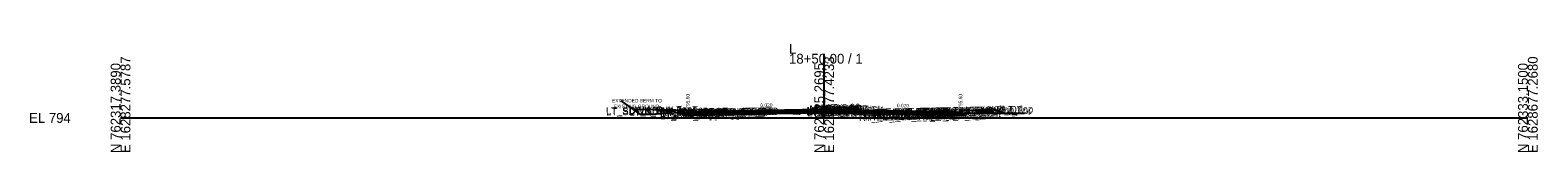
# Model space of a CAD drawing. Extents: x -26 to 4403, y -510 to 9556.
# Drawn here: x -25.7 to 402.8, y 8490.3 to 8521 of the extents above; entities that cross this region are included whole.
import ezdxf

# ---------------------------------------------------------------- set-up
doc = ezdxf.new("R2010")
doc.units = 0
for name, color, linetype in [('Default', 7, 'Continuous'), ('Exist Cross Section Cell', 7, 'Continuous'), ('Exist XS Ground Line', 7, 'Continuous'), ('Exist XS Void Line', 7, 'Continuous'), ('Prop CMT Conc Surface', 7, 'Continuous'), ('Prop CMT Concrete Structures', 7, 'Continuous'), ('Prop CMT Pvmt Course 1', 7, 'Continuous'), ('Prop CMT Pvmt Course 1 CG', 7, 'Continuous'), ('Prop CMT Pvmt Course 2', 7, 'Continuous'), ('Prop CMT Pvmt Course 3', 7, 'Continuous'), ('Prop CMT Pvmt Surface', 7, 'Continuous'), ('Prop CMT Pvmt Wedge Surface 1', 7, 'Continuous'), ('Prop CMT Pvmt Wedge Surface 2', 7, 'Continuous'), ('Prop CMT Pvmt Wedge Surface 3', 7, 'Continuous'), ('Prop CMT Slope Grass', 7, 'Continuous'), ('Prop CMT Subgrade Earthwork', 7, 'Continuous'), ('Prop XS Hydro Elevations', 7, 'Continuous'), ('Prop XS SE Text', 7, 'Continuous'), ('Prop XS Side Slope Text', 7, 'Continuous'), ('Scratch_Level_0', 7, 'Continuous')]:
    doc.layers.add(name, color=color, linetype=linetype)

msp = doc.modelspace()

# ---------------------------------------------------------------- linework, layer by layer
at = {"layer": 'Exist Cross Section Cell'}
for p, q in [((200, 8500), (200, 8518.22)), ((0, 8500), (200, 8500)), ((200, 8500), (400, 8500))]:
    msp.add_line(p, q, dxfattribs=at)
at = {"layer": 'Exist XS Ground Line'}
for p, q in [((142.23, 8504.87), (147.61, 8501.07)), ((147.61, 8501.07), (149.75, 8501.07))]:
    msp.add_line(p, q, dxfattribs=at)
msp.add_lwpolyline([(149.75, 8501.07), (150.28, 8501.1), (160.77, 8501.68), (170.58, 8501.81), (171.07, 8501.81), (172.04, 8501.77), (181.05, 8501.45), (184.18, 8501.38), (191.13, 8501.28), (192.9, 8501.15), (193.71, 8501.58), (195.23, 8501.44), (195.92, 8501.39)], dxfattribs=at)
at = {"layer": 'Exist XS Void Line'}
msp.add_line((195.92, 8501.39), (256.96, 8501.39), dxfattribs=at)
at = {"layer": 'Prop CMT Conc Surface'}
for points in [[(157.75, 8502.21), (152.75, 8502.31)], [(161.25, 8501.6), (161.25, 8502.1), (160.75, 8502.1)], [(238.75, 8501.6), (238.75, 8502.1), (239.25, 8502.1)], [(243.25, 8502.18), (248.25, 8502.28)], [(163.25, 8501.71), (161.25, 8501.6)], [(236.75, 8501.71), (238.75, 8501.6)]]:
    msp.add_lwpolyline(points, dxfattribs=at)
at = {"layer": 'Prop CMT Concrete Structures'}
for points in [[(152.75, 8501.97), (152.75, 8502.31)], [(152.75, 8502.31), (157.75, 8502.21)], [(157.75, 8502.21), (157.75, 8501.87)], [(163.25, 8501.71), (161.25, 8501.6), (161.25, 8502.1), (160.75, 8502.1)], [(160.75, 8502.1), (160.75, 8501.08), (163.25, 8501.13)], [(208, 8502.29), (207.99, 8502.46), (207.24, 8502.71), (206, 8502.97), (204.76, 8502.95), (204.01, 8502.7), (204, 8502.53)], [(204, 8502.53), (208, 8502.29)], [(236.75, 8501.71), (238.75, 8501.6), (238.75, 8502.1), (239.25, 8502.1)], [(239.25, 8502.1), (239.25, 8501.08), (236.75, 8501.13)], [(248.25, 8502.28), (243.25, 8502.18)], [(243.25, 8502.18), (243.25, 8501.85)], [(248.25, 8501.95), (248.25, 8502.28)], [(157.75, 8501.87), (152.75, 8501.97)], [(163.25, 8501.13), (163.25, 8501.71)], [(236.75, 8501.13), (236.75, 8501.71)], [(243.25, 8501.85), (248.25, 8501.95)]]:
    msp.add_lwpolyline(points, dxfattribs=at)
at = {"layer": 'Prop CMT Pvmt Course 1'}
for points in [[(204, 8502.53), (163.25, 8501.71)], [(163.25, 8501.46), (204, 8502.28)], [(175, 8501.7), (204, 8502.28)], [(204, 8502.53), (208, 8502.29)], [(204, 8502.28), (204, 8502.53)], [(204, 8502.28), (204, 8502.53)], [(208, 8502.04), (204, 8502.28)], [(208, 8502.29), (208, 8502.04)], [(208, 8502.29), (236.75, 8501.71)], [(208, 8502.04), (208, 8502.29)], [(163.25, 8501.71), (163.25, 8501.46)], [(236.75, 8501.46), (208, 8502.04)], [(225, 8501.7), (208, 8502.04)], [(236.75, 8501.71), (236.75, 8501.46)]]:
    msp.add_lwpolyline(points, dxfattribs=at)
at = {"layer": 'Prop CMT Pvmt Course 1 CG'}
for points in [[(163.25, 8501.13), (160.25, 8501.07), (159.91, 8500.73)], [(159.91, 8500.73), (163.25, 8500.8)], [(236.75, 8501.13), (239.75, 8501.07), (240.09, 8500.73)], [(236.75, 8500.8), (236.75, 8501.13)], [(240.09, 8500.73), (236.75, 8500.8)]]:
    msp.add_lwpolyline(points, dxfattribs=at)
at = {"layer": 'Prop CMT Pvmt Course 2'}
for points in [[(204, 8502.28), (163.25, 8501.46)], [(204, 8502.28), (175, 8501.7)], [(204, 8502.28), (208, 8502.04)], [(204, 8501.95), (204, 8502.28)], [(204, 8501.95), (204, 8502.28)], [(163.25, 8501.13), (204, 8501.95)], [(163.25, 8501.46), (163.25, 8501.13)], [(175, 8501.37), (204, 8501.95)], [(208, 8501.71), (204, 8501.95)], [(208, 8502.04), (208, 8501.71)], [(208, 8501.71), (208, 8502.04)], [(208, 8502.04), (225, 8501.7)], [(208, 8502.04), (236.75, 8501.46)], [(225, 8501.37), (208, 8501.71)], [(236.75, 8501.13), (208, 8501.71)], [(236.75, 8501.46), (236.75, 8501.13)]]:
    msp.add_lwpolyline(points, dxfattribs=at)
at = {"layer": 'Prop CMT Pvmt Course 3'}
for points in [[(204, 8501.95), (163.25, 8501.13)], [(163.25, 8500.8), (204, 8501.61)], [(163.25, 8501.13), (163.25, 8500.8)], [(204, 8501.95), (175, 8501.37)], [(175, 8501.03), (204, 8501.61)], [(204, 8501.95), (208, 8501.71)], [(204, 8501.61), (204, 8501.95)], [(204, 8501.61), (204, 8501.95)], [(208, 8501.37), (204, 8501.61)], [(208, 8501.71), (208, 8501.37)], [(208, 8501.71), (225, 8501.37)], [(208, 8501.37), (208, 8501.71)], [(208, 8501.71), (236.75, 8501.13)], [(225, 8501.03), (208, 8501.37)], [(236.75, 8500.8), (208, 8501.37)], [(236.75, 8501.13), (236.75, 8500.8)]]:
    msp.add_lwpolyline(points, dxfattribs=at)
at = {"layer": 'Prop CMT Pvmt Surface'}
for points in [[(204, 8502.53), (163.25, 8501.71)], [(204, 8502.53), (208, 8502.29)], [(208, 8502.29), (236.75, 8501.71)]]:
    msp.add_lwpolyline(points, dxfattribs=at)
at = {"layer": 'Prop CMT Pvmt Wedge Surface 1'}
for points in [[(204, 8502.28), (163.25, 8501.46)], [(204, 8502.28), (175, 8501.7)], [(204, 8502.53), (204, 8502.28)], [(208, 8502.29), (208, 8502.04)], [(163.25, 8501.46), (163.25, 8501.71)], [(208, 8502.04), (225, 8501.7)], [(208, 8502.04), (236.75, 8501.46)], [(236.75, 8501.46), (236.75, 8501.71)]]:
    msp.add_lwpolyline(points, dxfattribs=at)
at = {"layer": 'Prop CMT Pvmt Wedge Surface 2'}
for points in [[(204, 8502.53), (204, 8502.28)], [(208, 8502.29), (208, 8502.04)], [(163.25, 8501.46), (163.25, 8501.71)], [(236.75, 8501.46), (236.75, 8501.71)]]:
    msp.add_lwpolyline(points, dxfattribs=at)
at = {"layer": 'Prop CMT Pvmt Wedge Surface 3'}
for points in [[(204, 8502.53), (204, 8501.95)], [(208, 8502.29), (208, 8501.71)], [(163.25, 8501.13), (163.25, 8501.71)], [(236.75, 8501.13), (236.75, 8501.71)]]:
    msp.add_lwpolyline(points, dxfattribs=at)
at = {"layer": 'Prop CMT Slope Grass'}
for points in [[(151.25, 8502.28), (145.74, 8502.4)], [(160.75, 8502.1), (151.25, 8502.28)], [(239.25, 8502.1), (248.25, 8502.27)], [(248.25, 8502.27), (248.74, 8502.28), (251.41, 8501.39)]]:
    msp.add_lwpolyline(points, dxfattribs=at)
at = {"layer": 'Prop CMT Subgrade Earthwork'}
for points in [[(163.25, 8500.8), (159.91, 8500.73), (158.5, 8502.14)], [(236.75, 8500.8), (240.09, 8500.73), (241.5, 8502.14)], [(204, 8501.61), (163.25, 8500.8)], [(163.25, 8500.8), (163.25, 8500.8)], [(163.25, 8500.8), (163.25, 8500.8)], [(163.25, 8500.8), (163.25, 8500.8)], [(163.25, 8500.8), (163.25, 8500.8)], [(204, 8501.61), (208, 8501.37)], [(208, 8501.37), (236.75, 8500.8)]]:
    msp.add_lwpolyline(points, dxfattribs=at)

# ---------------------------------------------------------------- texts
at = {"layer": 'Default'}
msp.add_text('-', height=0.0001, dxfattribs=at).set_placement((0, 8500))
at = {"layer": 'Exist Cross Section Cell'}
for s, p in [('L', (190, 8518.22)), ('18+50.00 / 1', (190, 8515.42)), ('EL 794', (-26, 8498.6))]:
    msp.add_text(s, height=2.8, dxfattribs=at).set_placement(p)
for s, p in [('N 762317.3890', (0, 8490)), ('E 1628277.5787', (2.8, 8490)), ('N 762325.2695', (200, 8490)), ('E 1628477.4233', (202.8, 8490)), ('N 762333.1500', (400, 8490)), ('E 1628677.2680', (402.8, 8490))]:
    msp.add_text(s, height=2.8, rotation=90, dxfattribs=at).set_placement(p)
at = {"layer": 'Prop XS Hydro Elevations'}
for p in [(161.75, 8502.6), (239.25, 8502.6)]:
    msp.add_text('795.60', height=1, rotation=90, dxfattribs=at).set_placement(p)
at = {"layer": 'Prop XS SE Text'}
for rotation, p in [(1.1458, (181.86, 8503.09)), (358.8542, (220.65, 8503.04))]:
    msp.add_text('0.020', height=1, rotation=rotation, dxfattribs=at).set_placement(p)
at = {"layer": 'Prop XS Side Slope Text'}
for s, p in [('EXTENDED BERM TO', (139.68, 8504.39)), ('EXISTING GROUND', (140.19, 8502.76))]:
    msp.add_text(s, height=1, dxfattribs=at).set_placement(p)
msp.add_text('3:1', height=1, rotation=341.5651, dxfattribs=at).set_placement((249.53, 8502.7))
at = {"layer": 'Scratch_Level_0'}
for s, p in [('LT_SDWK_Out_Top', (138.01, 8501.01)), ('LT_SDWK_Out_Bot', (138.04, 8500.68)), ('LT_SDWK_In_Top', (144.63, 8500.94)), ('LT_SDWK_In_Bot', (144.66, 8500.61)), ('LT_PV2_OEOT', (153.45, 8500.27)), ('LT_PV3_OEOT', (153.45, 8499.94)), ('LT_PV1_OEOT', (154.01, 8500.53)), ('LT_PV_Sub_Tie_Out', (159.98, 8500.37)), ('LT_PV_EG_TestPt', (161.43, 8500.4)), ('LT_PV_Sub_Tie_In', (161.57, 8500.4)), ('LT_PV_OEEOP_EG', (162.57, 8500.42)), ('LT_PV_IEEOP_EG', (163.21, 8500.43)), ('LT_Sub_OEEOP', (164.23, 8499.82)), ('LT_PV2_OEEOP', (164.33, 8500.49)), ('LT_PV3_OEEOP', (164.33, 8500.15)), ('LT_Sub_IEEOP', (164.88, 8499.83)), ('LT_PV1_OEEOP', (164.9, 8500.62)), ('LT_PV2_IEEOP', (164.97, 8500.5)), ('LT_PV3_IEEOP', (164.97, 8500.17)), ('LT_PV1_IEEOP', (165.54, 8500.64)), ('LT_PV2_PGL1', (194.9, 8501.1)), ('LT_PV3_PGL1', (194.9, 8500.76)), ('LT_Sub_PGL', (195.14, 8500.44)), ('LT_PV2_PGL', (195.23, 8501.1)), ('LT_PV3_PGL', (195.23, 8500.77)), ('LT_PV4_PGL', (195.23, 8500.44)), ('LT_PV1_PGL', (195.8, 8501.37)), ('MI_Face In', (195.92, 8501.54)), ('MI_Top In', (197.63, 8501.8)), ('MI_Face Out', (198.28, 8501.26)), ('MI_Top Out', (198.49, 8501.53)), ('RT_PV2_PGL1', (198.86, 8500.86)), ('RT_PV3_PGL1', (198.86, 8500.52)), ('MI_Crown', (199.09, 8501.83)), ('RT_Sub_PGL', (199.09, 8500.19)), ('18+50.00', (199.08, 8501.83)), ('RT_PV2_PGL', (199.19, 8500.86)), ('RT_PV3_PGL', (199.19, 8500.53)), ('RT_PV4_PGL', (199.19, 8500.2)), ('MI_Bot Out', (199.28, 8501.12)), ('RT_PV1_PGL', (199.75, 8501.12)), ('18+50.00', (201.39, 8501.48)), ('18+50.00', (201.83, 8501.25)), ('RT_PV_EG_TestPt', (211.38, 8499.83)), ('RT_PV_OEEOP_EG', (212.52, 8499.77)), ('RT_PV_IEEOP_EG', (213.16, 8499.94)), ('RT_Sub_OEEOP', (214.19, 8499.82)), ('RT_PV2_OEEOP', (214.28, 8500.49)), ('RT_PV3_OEEOP', (214.28, 8500.15)), ('RT_Sub_IEEOP', (214.83, 8499.83)), ('RT_PV1_OEEOP', (214.85, 8500.62)), ('RT_PV2_IEEOP', (214.93, 8500.5)), ('RT_PV3_IEEOP', (214.93, 8500.17)), ('RT_PV1_IEEOP', (215.49, 8500.63)), ('RT_Sub_Trench_Out_DLT', (222.04, 8500.75)), ('RT_CG_Top_Face', (225.99, 8500.84)), ('RT_CG1_Shelf_Out', (226.28, 8499.8)), ('RT_CG_Bot_IE', (226.64, 8499.93)), ('RT_PV2_OEOT', (226.9, 8500.27)), ('RT_PV3_OEOT', (226.9, 8499.93)), ('RT_CG_Top_Gut', (226.96, 8500.36)), ('RT_PV1_OEOT', (227.46, 8500.53)), ('RT_CG_Top_BOC', (227.51, 8500.86)), ('RT_CG_Bot_BOC', (227.54, 8499.85)), ('RT_SDWK_In_Top', (231.08, 8500.94)), ('RT_SDWK_In_Bot', (231.12, 8500.61)), ('18+50.00', (231.75, 8500.52)), ('18+50.00', (233.52, 8500.98)), ('RT_SDWK_Out_Top', (234.46, 8501.01)), ('RT_SDWK_Out_Bot', (234.49, 8500.68)), ('RT_Shld_O', (240.81, 8501.13)), ('LT_Sub_OEOT', (153.35, 8499.6)), ('RT_PV_Sub_Tie_Out', (209.91, 8499.09)), ('RT_PV_Sub_Tie_In', (211.56, 8499.29)), ('RT_Sub_OEOT_CG', (224.1, 8499.54)), ('RT_Sub_OEOT', (226.8, 8499.6)), ('RT_Sub_OEOP', (230.17, 8499.53))]:
    msp.add_text(s, height=2, rotation=1.1458, dxfattribs=at).set_placement(p)

doc.saveas('drawing.dxf')
